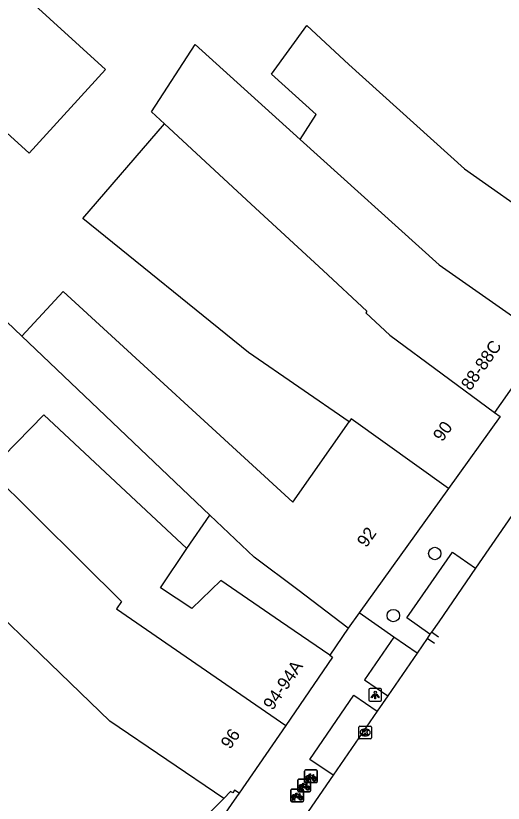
# Model space of a CAD drawing. Extents: x 160107 to 160928, y 382056 to 382918.
# Drawn here: x 160762.6 to 160801.1, y 382602.3 to 382664.5 of the extents above; entities that cross this region are included whole.
import ezdxf

# ---------------------------------------------------------------- set-up
doc = ezdxf.new("R2010")
doc.units = 0
for name, color, linetype in [('IMGEO_Boom', 7, 'Continuous'), ('IMGEO_Fietsenrek', 7, 'Continuous'), ('IMGEO_Kolk', 7, 'Continuous'), ('IMGEO_Lichtpunt', 7, 'Continuous'), ('IMGEO_Pand', 7, 'Continuous'), ('IMGEO_Pand_nummerreeks', 7, 'Continuous'), ('IMGEO_Rijbaan_lokaal_gesloten', 7, 'Continuous'), ('IMGEO_Rijbaan_lokaal_open', 7, 'Continuous'), ('IMGEO_Voetpad_open', 7, 'Continuous')]:
    doc.layers.add(name, color=color, linetype=linetype)

msp = doc.modelspace()

# ---------------------------------------------------------------- linework, layer by layer
at = {"layer": 'IMGEO_Boom'}
for centre in [(160795.702, 382622.011), (160792.426, 382617.104)]:
    msp.add_circle(centre, 0.489, dxfattribs=at)
at = {"layer": 'IMGEO_Fietsenrek'}
for p, q in [((160785.424, 382603.983), (160785.424, 382604.824)), ((160785.424, 382604.824), (160785.424, 382603.983)), ((160785.499, 382604.908), (160786.34, 382604.908)), ((160786.34, 382604.908), (160785.499, 382604.908)), ((160786.424, 382604.833), (160786.424, 382603.992)), ((160786.424, 382603.992), (160786.424, 382604.833)), ((160784.894, 382603.262), (160784.894, 382604.103)), ((160784.894, 382604.103), (160784.894, 382603.262)), ((160784.969, 382604.187), (160785.81, 382604.187)), ((160785.81, 382604.187), (160784.969, 382604.187)), ((160785.551, 382603.992), (160785.59, 382604.152)), ((160785.62, 382604.14), (160785.585, 382603.992)), ((160785.662, 382604.164), (160785.661, 382604.168)), ((160785.703, 382603.992), (160785.669, 382604.134)), ((160785.693, 382604.175), (160785.694, 382604.168)), ((160785.701, 382604.138), (160785.736, 382603.992)), ((160785.894, 382604.112), (160785.894, 382603.271)), ((160785.894, 382603.271), (160785.894, 382604.112)), ((160786.111, 382604.457), (160786.147, 382604.362)), ((160785.132, 382603.443), (160785.131, 382603.447)), ((160785.163, 382603.454), (160785.164, 382603.447)), ((160786.349, 382603.908), (160785.508, 382603.908)), ((160785.508, 382603.908), (160786.349, 382603.908)), ((160785.585, 382603.992), (160785.551, 382603.992)), ((160785.581, 382603.736), (160785.617, 382603.641)), ((160785.736, 382603.992), (160785.703, 382603.992)), ((160784.338, 382602.475), (160784.338, 382603.316)), ((160784.338, 382603.316), (160784.338, 382602.475)), ((160784.413, 382603.4), (160785.254, 382603.4)), ((160785.254, 382603.4), (160784.413, 382603.4)), ((160785.819, 382603.187), (160784.978, 382603.187)), ((160784.978, 382603.187), (160785.819, 382603.187)), ((160785.021, 382603.271), (160785.06, 382603.431)), ((160785.055, 382603.271), (160785.021, 382603.271)), ((160785.025, 382602.949), (160785.061, 382602.854)), ((160785.09, 382603.419), (160785.055, 382603.271)), ((160785.173, 382603.271), (160785.139, 382603.413)), ((160785.171, 382603.417), (160785.206, 382603.271)), ((160785.206, 382603.271), (160785.173, 382603.271)), ((160785.338, 382603.325), (160785.338, 382602.484)), ((160785.338, 382602.484), (160785.338, 382603.325)), ((160785.263, 382602.4), (160784.422, 382602.4)), ((160784.422, 382602.4), (160785.263, 382602.4)), ((160784.465, 382602.484), (160784.504, 382602.644)), ((160784.499, 382602.484), (160784.465, 382602.484)), ((160784.534, 382602.632), (160784.499, 382602.484)), ((160784.576, 382602.656), (160784.575, 382602.66)), ((160784.617, 382602.484), (160784.583, 382602.626)), ((160784.607, 382602.667), (160784.608, 382602.66)), ((160784.615, 382602.63), (160784.65, 382602.484)), ((160784.65, 382602.484), (160784.617, 382602.484))]:
    msp.add_line(p, q, dxfattribs=at)
for points in [[(160785.758, 382604.382), (160785.706, 382604.292), (160785.666, 382604.267), (160785.667, 382604.314), (160785.722, 382604.408)], [(160785.737, 382604.434), (160785.832, 382604.598), (160785.918, 382604.584), (160785.92, 382604.575), (160785.864, 382604.564), (160785.837, 382604.519), (160786.093, 382604.478)], [(160786.033, 382604.19), (160785.983, 382604.19), (160785.792, 382604.441), (160785.773, 382604.409)], [(160786.08, 382604.453), (160785.823, 382604.494), (160785.806, 382604.465), (160785.973, 382604.245), (160786.08, 382604.453)], [(160786.128, 382604.355), (160786.098, 382604.432), (160785.989, 382604.214), (160786.032, 382604.214)], [(160786.062, 382604.214), (160786.182, 382604.213), (160786.138, 382604.327)], [(160786.158, 382604.334), (160786.213, 382604.189), (160786.063, 382604.189)], [(160786.093, 382604.478), (160786.118, 382604.527), (160786.112, 382604.531), (160786.089, 382604.535), (160786.077, 382604.542), (160786.076, 382604.545), (160786.078, 382604.55), (160786.173, 382604.535), (160786.175, 382604.525), (160786.165, 382604.512), (160786.153, 382604.506), (160786.139, 382604.512), (160786.111, 382604.457)], [(160785.228, 382603.661), (160785.176, 382603.571), (160785.136, 382603.546), (160785.137, 382603.593), (160785.192, 382603.687)], [(160785.207, 382603.713), (160785.302, 382603.877), (160785.388, 382603.863), (160785.39, 382603.854), (160785.334, 382603.843), (160785.307, 382603.798), (160785.563, 382603.757)], [(160785.503, 382603.469), (160785.453, 382603.469), (160785.262, 382603.72), (160785.243, 382603.688)], [(160785.55, 382603.732), (160785.293, 382603.773), (160785.276, 382603.744), (160785.443, 382603.524), (160785.55, 382603.732)], [(160785.598, 382603.634), (160785.568, 382603.711), (160785.459, 382603.493), (160785.502, 382603.493)], [(160785.532, 382603.493), (160785.652, 382603.492), (160785.608, 382603.606)], [(160785.628, 382603.613), (160785.683, 382603.468), (160785.533, 382603.468)], [(160785.563, 382603.757), (160785.588, 382603.806), (160785.582, 382603.81), (160785.559, 382603.814), (160785.547, 382603.821), (160785.546, 382603.824), (160785.548, 382603.829), (160785.643, 382603.814), (160785.645, 382603.804), (160785.635, 382603.791), (160785.623, 382603.785), (160785.609, 382603.791), (160785.581, 382603.736)], [(160784.672, 382602.874), (160784.62, 382602.784), (160784.58, 382602.759), (160784.581, 382602.806), (160784.636, 382602.9)], [(160784.651, 382602.926), (160784.746, 382603.09), (160784.832, 382603.076), (160784.834, 382603.067), (160784.778, 382603.056), (160784.751, 382603.011), (160785.007, 382602.97)], [(160784.947, 382602.682), (160784.897, 382602.682), (160784.706, 382602.933), (160784.687, 382602.901)], [(160784.994, 382602.945), (160784.737, 382602.986), (160784.72, 382602.957), (160784.887, 382602.737), (160784.994, 382602.945)], [(160785.042, 382602.847), (160785.012, 382602.924), (160784.903, 382602.706), (160784.946, 382602.706)], [(160784.976, 382602.706), (160785.096, 382602.705), (160785.052, 382602.819)], [(160785.072, 382602.826), (160785.127, 382602.681), (160784.977, 382602.681)], [(160785.007, 382602.97), (160785.032, 382603.019), (160785.026, 382603.023), (160785.003, 382603.027), (160784.991, 382603.034), (160784.99, 382603.037), (160784.992, 382603.042), (160785.087, 382603.027), (160785.089, 382603.017), (160785.079, 382603.004), (160785.067, 382602.998), (160785.053, 382603.004), (160785.025, 382602.949)]]:
    msp.add_lwpolyline(points, dxfattribs=at)
for centre, radius, start, end in [((160785.502, 382604.83), 0.0779, 92.4484, 184.28452), ((160785.502, 382604.83), 0.0779, 92.4484, 184.28452), ((160786.346, 382604.83), 0.0779, 2.4484, 94.28452), ((160786.346, 382604.83), 0.0779, 2.4484, 94.28452), ((160784.972, 382604.109), 0.0779, 92.4484, 184.28452), ((160784.972, 382604.109), 0.0779, 92.4484, 184.28452), ((160785.664, 382604.293), 0.159, 62.67661, 242.13685), ((160785.664, 382604.293), 0.129, 63.31916, 238.90302), ((160785.644, 382604.164), 0.0499, 12.8025, 158.69338), ((160785.664, 382604.293), 0.159, 253.99666, 271.78671), ((160785.644, 382604.164), 0.0174, 12.8025, 163.45023), ((160785.664, 382604.293), 0.129, 253.41502, 269.02044), ((160785.664, 382604.293), 0.129, 283.60429, 43.43025), ((160785.664, 382604.293), 0.159, 283.5766, 46.60424), ((160785.816, 382604.109), 0.0779, 2.4484, 94.28452), ((160785.816, 382604.109), 0.0779, 2.4484, 94.28452), ((160786.191, 382604.209), 0.159, 113.3408, 178.32165), ((160786.191, 382604.209), 0.159, 187.0065, 105.77075), ((160786.191, 382604.209), 0.129, 113.92302, 177.95563), ((160786.191, 382604.209), 0.129, 188.67146, 104.58832), ((160785.134, 382603.572), 0.159, 62.67661, 242.13685), ((160785.134, 382603.572), 0.129, 63.31916, 238.90302), ((160785.114, 382603.443), 0.0499, 12.8025, 158.69338), ((160785.114, 382603.443), 0.0174, 12.8025, 163.45023), ((160785.134, 382603.572), 0.129, 253.41502, 269.02044), ((160785.134, 382603.572), 0.129, 283.60429, 43.43025), ((160785.134, 382603.572), 0.159, 283.5766, 46.60424), ((160785.502, 382603.986), 0.0779, 182.4484, 274.28452), ((160785.502, 382603.986), 0.0779, 182.4484, 274.28452), ((160785.661, 382603.488), 0.159, 113.3408, 178.32165), ((160785.661, 382603.488), 0.159, 187.0065, 105.77075), ((160785.661, 382603.488), 0.129, 113.92302, 177.95563), ((160785.661, 382603.488), 0.129, 188.67146, 104.58832), ((160786.346, 382603.986), 0.0779, 272.4484, 4.28452), ((160786.346, 382603.986), 0.0779, 272.4484, 4.28452), ((160784.416, 382603.322), 0.0779, 92.4484, 184.28452), ((160784.416, 382603.322), 0.0779, 92.4484, 184.28452), ((160784.578, 382602.785), 0.159, 62.67661, 242.13685), ((160784.578, 382602.785), 0.129, 63.31916, 238.90302), ((160784.578, 382602.785), 0.129, 283.60429, 43.43025), ((160784.578, 382602.785), 0.159, 283.5766, 46.60424), ((160784.972, 382603.265), 0.0779, 182.4484, 274.28452), ((160784.972, 382603.265), 0.0779, 182.4484, 274.28452), ((160785.105, 382602.701), 0.159, 113.3408, 178.32165), ((160785.105, 382602.701), 0.159, 187.0065, 105.77075), ((160785.105, 382602.701), 0.129, 113.92302, 177.95563), ((160785.105, 382602.701), 0.129, 188.67146, 104.58832), ((160785.134, 382603.572), 0.159, 253.99666, 271.78671), ((160785.26, 382603.322), 0.0779, 2.4484, 94.28452), ((160785.26, 382603.322), 0.0779, 2.4484, 94.28452), ((160785.816, 382603.265), 0.0779, 272.4484, 4.28452), ((160785.816, 382603.265), 0.0779, 272.4484, 4.28452), ((160784.416, 382602.478), 0.0779, 182.4484, 274.28452), ((160784.416, 382602.478), 0.0779, 182.4484, 274.28452), ((160784.558, 382602.656), 0.0499, 12.8025, 158.69338), ((160784.578, 382602.785), 0.159, 253.99666, 271.78671), ((160784.558, 382602.656), 0.0174, 12.8025, 163.45023), ((160784.578, 382602.785), 0.129, 253.41502, 269.02044), ((160785.26, 382602.478), 0.0779, 272.4484, 4.28452), ((160785.26, 382602.478), 0.0779, 272.4484, 4.28452)]:
    msp.add_arc(centre, radius, start, end, dxfattribs=at)
at = {"layer": 'IMGEO_Kolk'}
for p, q in [((160789.705, 382607.448), (160789.705, 382608.3)), ((160789.78, 382608.374), (160790.632, 382608.374)), ((160790.193, 382608.154), (160790.218, 382608.154)), ((160790.706, 382608.3), (160790.706, 382607.448)), ((160790.632, 382607.374), (160789.78, 382607.374)), ((160790.216, 382607.594), (160790.191, 382607.594))]:
    msp.add_line(p, q, dxfattribs=at)
for points in [[(160789.705, 382607.448), (160789.705, 382608.3)], [(160789.78, 382608.374), (160790.632, 382608.374)], [(160790.026, 382608.074), (160790.149, 382608.074), (160790.149, 382607.923), (160790.279, 382608.074), (160790.443, 382608.074), (160790.297, 382607.923), (160790.45, 382607.674), (160790.298, 382607.674), (160790.213, 382607.838), (160790.149, 382607.771), (160790.149, 382607.674), (160790.026, 382607.674), (160790.026, 382608.074)], [(160790.706, 382608.3), (160790.706, 382607.448)], [(160790.632, 382607.374), (160789.78, 382607.374)]]:
    msp.add_lwpolyline(points, dxfattribs=at)
for centre, start, end in [((160789.782, 382608.298), 91.55205, 178.44795), ((160789.782, 382608.298), 91.55205, 178.44795), ((160790.63, 382608.298), 1.55205, 88.44795), ((160790.63, 382608.298), 1.55205, 88.44795), ((160789.782, 382607.45), 181.55205, 268.44795), ((160789.782, 382607.45), 181.55205, 268.44795), ((160790.63, 382607.45), 271.55205, 358.44795), ((160790.63, 382607.45), 271.55205, 358.44795)]:
    msp.add_arc(centre, 0.0765, start, end, dxfattribs=at)
for centre, major_axis, ratio, start_param, end_param in [((160790.192, 382607.874), (-0.387, 0.002), 0.722429, 4.712389, 7.853982), ((160790.217, 382607.874), (-0.39, 0.002), 0.717154, 1.570796, 4.712389)]:
    msp.add_ellipse(centre, major_axis=major_axis, ratio=ratio, start_param=start_param, end_param=end_param, dxfattribs=at)
at = {"layer": 'IMGEO_Lichtpunt'}
for p, q in [((160790.503, 382611.244), (160790.503, 382610.437)), ((160790.503, 382611.244), (160790.503, 382610.437)), ((160791.405, 382611.339), (160790.597, 382611.339)), ((160791.405, 382611.339), (160790.597, 382611.339)), ((160791.499, 382610.437), (160791.499, 382611.244)), ((160791.499, 382610.437), (160791.499, 382611.244)), ((160790.597, 382610.343), (160791.405, 382610.343)), ((160790.597, 382610.343), (160791.405, 382610.343))]:
    msp.add_line(p, q, dxfattribs=at)
for points in [[(160790.877, 382610.908), (160790.916, 382610.88), (160790.728, 382610.618), (160790.69, 382610.645), (160790.877, 382610.908)], [(160791.089, 382610.88), (160791.127, 382610.907), (160791.314, 382610.645), (160791.275, 382610.617), (160791.089, 382610.88)], [(160790.979, 382610.86), (160791.026, 382610.86), (160791.026, 382610.538), (160790.979, 382610.538), (160790.979, 382610.86)]]:
    msp.add_lwpolyline(points, dxfattribs=at)
msp.add_circle((160791.002, 382611.042), 0.0994, dxfattribs=at)
for centre, start, end in [((160790.597, 382611.244), 90, 180), ((160790.597, 382611.244), 90, 180), ((160791.405, 382611.244), 0, 90), ((160791.405, 382611.244), 0, 90), ((160790.597, 382610.437), 180, 270), ((160790.597, 382610.437), 180, 270), ((160791.405, 382610.437), 270, 0), ((160791.405, 382610.437), 270, 360)]:
    msp.add_arc(centre, 0.0946, start, end, dxfattribs=at)
at = {"layer": 'IMGEO_Pand'}
for points in [[(160730.83, 382683.568), (160736.85, 382690.176), (160769.696, 382660.249), (160763.676, 382653.641), (160730.83, 382683.568)], [(160785.069, 382654.734), (160786.338, 382656.69), (160782.806, 382659.883), (160785.595, 382663.742), (160788.911, 382660.658), (160798.037, 382652.404), (160804.186, 382648.094)], [(160774.369, 382655.963), (160773.342, 382656.915), (160776.785, 382662.223), (160785.069, 382654.734)], [(160788.939, 382632.421), (160780.991, 382637.891), (160767.915, 382648.477), (160774.369, 382655.963)], [(160774.369, 382655.963), (160781.549, 382649.307), (160786.885, 382644.361), (160790.337, 382641.162), (160790.249, 382641.036), (160792.159, 382639.27), (160800.424, 382633.157)], [(160785.069, 382654.734), (160796.043, 382644.814), (160804.459, 382638.914)], [(160757.915, 382594.327), (160754.266, 382596.84), (160747.353, 382605.306), (160742.894, 382610.767), (160744.207, 382630.725), (160757.68, 382644.347), (160763.102, 382639.177)], [(160763.102, 382639.177), (160766.357, 382642.722), (160784.49, 382626.073), (160788.939, 382632.421)], [(160777.954, 382625.051), (160763.102, 382639.177)], [(160804.459, 382638.914), (160800.424, 382633.157)], [(160760.51, 382628.58), (160764.842, 382632.96), (160772.905, 382625.416), (160776.12, 382622.408)], [(160800.424, 382633.157), (160800.86, 382632.833), (160796.772, 382627.136)], [(160796.772, 382627.136), (160789.105, 382632.659), (160788.939, 382632.421)], [(160779.038, 382602.663), (160770.055, 382608.763), (160755.147, 382623.157), (160760.51, 382628.58)], [(160760.51, 382628.58), (160767.849, 382621.306), (160770.966, 382618.217), (160770.573, 382617.65), (160783.932, 382608.424)], [(160796.772, 382627.136), (160789.726, 382617.315)], [(160776.12, 382622.408), (160777.954, 382625.051)], [(160788.866, 382616.116), (160784.879, 382619.133), (160781.446, 382621.73), (160777.954, 382625.051)], [(160787.402, 382613.975), (160783.518, 382616.648), (160778.809, 382619.89), (160776.53, 382617.655), (160774.037, 382619.296), (160776.12, 382622.408)], [(160789.726, 382617.315), (160788.866, 382616.116)], [(160787.402, 382613.975), (160787.637, 382613.813), (160783.932, 382608.424)], [(160783.932, 382608.424), (160780.249, 382603.067)], [(160780.249, 382603.067), (160779.893, 382603.312), (160779.752, 382603.092), (160779.582, 382603.212), (160779.038, 382602.663)], [(160757.915, 382594.327), (160763.168, 382590.709), (160764.076, 382591.898), (160766.66, 382590.155), (160779.038, 382602.663)]]:
    msp.add_lwpolyline(points, dxfattribs=at)
at = {"layer": 'IMGEO_Rijbaan_lokaal_gesloten'}
for points in [[(160805.417, 382630.29), (160798.913, 382620.841)], [(160798.913, 382620.841), (160796.011, 382616.61), (160795.431, 382615.795)], [(160795.092, 382615.3), (160794.297, 382614.14)], [(160795.673, 382614.907), (160795.092, 382615.3)], [(160796.001, 382615.398), (160795.431, 382615.795)], [(160794.297, 382614.14), (160791.987, 382610.769)], [(160791.987, 382610.769), (160791.163, 382609.567)], [(160791.163, 382609.567), (160787.691, 382604.499)], [(160787.691, 382604.499), (160763.257, 382568.959)]]:
    msp.add_lwpolyline(points, dxfattribs=at)
at = {"layer": 'IMGEO_Rijbaan_lokaal_open'}
for points in [[(160795.315, 382615.626), (160795.092, 382615.3)], [(160795.431, 382615.795), (160795.315, 382615.626)]]:
    msp.add_lwpolyline(points, dxfattribs=at)
at = {"layer": 'IMGEO_Voetpad_open'}
for points in [[(160795.315, 382615.626), (160793.502, 382616.918), (160797.098, 382622.107), (160798.913, 382620.841)], [(160792.466, 382615.412), (160789.726, 382617.315)], [(160788.866, 382616.116), (160787.402, 382613.975)], [(160792.466, 382615.412), (160790.144, 382612.038), (160791.987, 382610.769)], [(160794.297, 382614.14), (160792.466, 382615.412)], [(160787.691, 382604.499), (160785.838, 382605.748), (160789.309, 382610.824), (160791.163, 382609.567)], [(160780.249, 382603.067), (160780.054, 382602.786), (160769.686, 382587.844), (160769.298, 382587.285), (160767.334, 382584.454)]]:
    msp.add_lwpolyline(points, dxfattribs=at)

# ---------------------------------------------------------------- texts
at = {"layer": 'IMGEO_Pand_nummerreeks'}
for s, rotation, p in [('88-88C', 54.9753, (160798.51, 382634.818)), ('90', 54.33932, (160796.289, 382630.784)), ('92', 54.33932, (160790.288, 382622.421)), ('94-94A', 55.49096, (160782.896, 382609.565)), ('96', 55.49096, (160779.546, 382606.492))]:
    msp.add_text(s, height=1, rotation=rotation, dxfattribs=at).set_placement(p)

doc.saveas('drawing.dxf')
